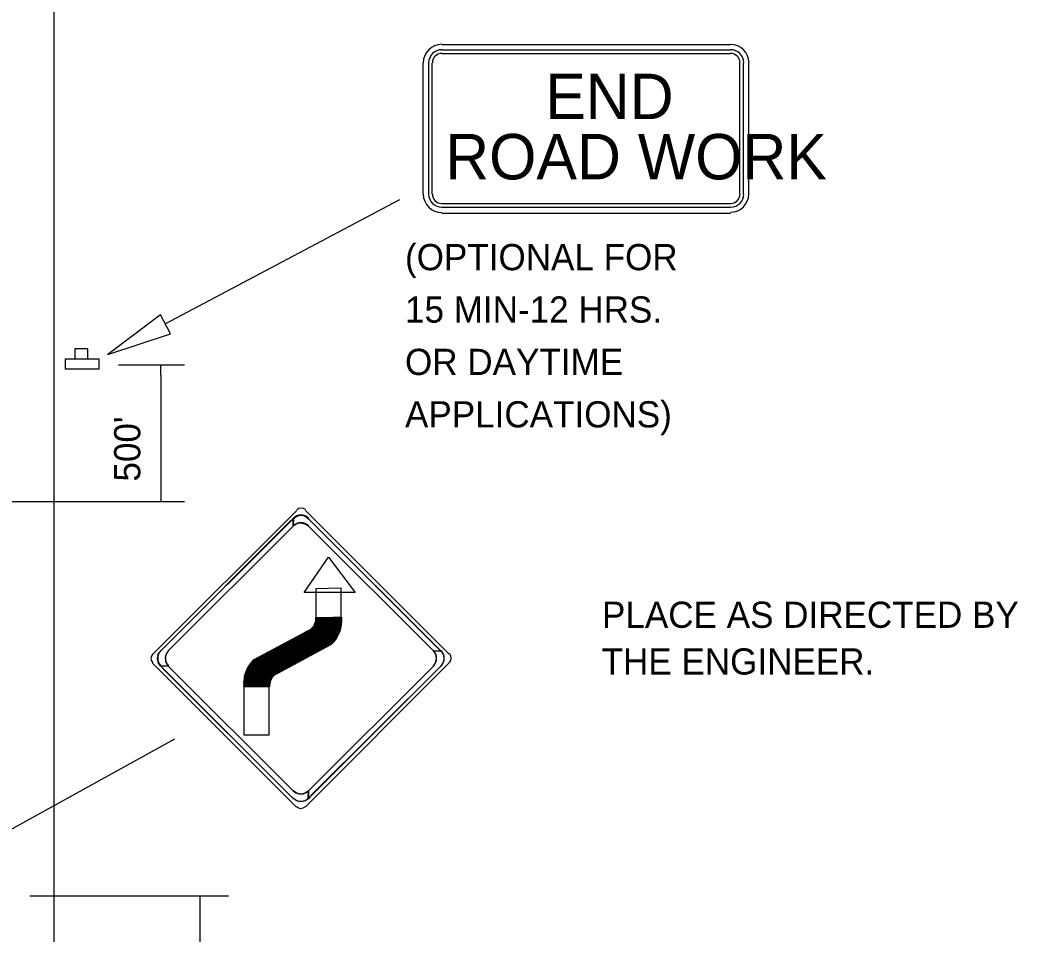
# Model space of a CAD drawing. Extents: x 15312.2 to 15319.5, y 15309 to 15319.2.
# Drawn here: x 15316.1 to 15318.384, y 15314.978 to 15317.071 of the extents above; entities that cross this region are included whole.
import ezdxf

# ---------------------------------------------------------------- set-up
doc = ezdxf.new("R2010")
doc.units = 0
for name, color, linetype in [('DETL-DIMS', 7, 'Continuous'), ('DETL-LINE', 7, 'Continuous'), ('DETL-NOTE', 7, 'Continuous'), ('USER-BORD', 7, 'Continuous')]:
    doc.layers.add(name, color=color, linetype=linetype)

# ---------------------------------------------------------------- blocks, each defined once
blk = doc.blocks.new('SIGN13')
at = {"layer": 'USER-BORD'}
for points in [[(-0.013, 0.018), (0.011, 0.019), (0.011, 0.037), (-0.013, 0.037)], [(-0.031, 0.018), (-0.031, 0), (0.032, 0), (0.032, 0.018)]]:
    blk.add_lwpolyline(points, close=True, dxfattribs=at)

msp = doc.modelspace()

# ---------------------------------------------------------------- linework, layer by layer
at = {"layer": 'DETL-DIMS'}
for p, q in [((15316.432, 15316.375), (15316.969, 15316.66)), ((15316.325, 15316.281), (15316.476, 15316.281)), ((15316.422, 15316.258), (15316.422, 15316.281)), ((15316.422, 15316.258), (15316.422, 15315.968)), ((15315.961, 15315.968), (15316.476, 15315.968)), ((15315.994, 15315.171), (15316.454, 15315.425)), ((15316.122, 15315.065), (15316.577, 15315.065)), ((15316.512, 15314.788), (15316.512, 15315.065))]:
    msp.add_line(p, q, dxfattribs=at)
msp.add_lwpolyline([(15316.444, 15316.352), (15316.421, 15316.396), (15316.301, 15316.305)], close=True, dxfattribs=at)
at = {"layer": 'DETL-LINE'}
for p, q in [((15316.177, 15318.785), (15316.177, 15310.694)), ((15317.726, 15317.014), (15317.065, 15317.014)), ((15317.726, 15317.002), (15317.065, 15317.002)), ((15317.065, 15316.994), (15317.726, 15316.994)), ((15317.726, 15317.002), (15317.726, 15317.002)), ((15317.022, 15316.972), (15317.022, 15316.672)), ((15317.035, 15316.972), (15317.035, 15316.672)), ((15317.043, 15316.672), (15317.043, 15316.972)), ((15317.747, 15316.972), (15317.747, 15316.672)), ((15317.756, 15316.672), (15317.756, 15316.972)), ((15317.768, 15316.672), (15317.768, 15316.972)), ((15317.726, 15316.65), (15317.065, 15316.65)), ((15317.065, 15316.642), (15317.726, 15316.642)), ((15317.065, 15316.629), (15317.726, 15316.629)), ((15316.733, 15315.948), (15316.403, 15315.618)), ((15317.082, 15315.619), (15316.753, 15315.948)), ((15316.422, 15315.626), (15316.725, 15315.929)), ((15316.725, 15315.912), (15316.439, 15315.626)), ((15316.76, 15315.929), (15317.063, 15315.626)), ((15317.046, 15315.626), (15316.76, 15315.912)), ((15316.813, 15315.641), (15316.771, 15315.683)), ((15316.814, 15315.642), (15316.772, 15315.684)), ((15316.816, 15315.645), (15316.773, 15315.688)), ((15316.815, 15315.644), (15316.773, 15315.686)), ((15316.814, 15315.642), (15316.773, 15315.685)), ((15316.815, 15315.643), (15316.773, 15315.685)), ((15316.817, 15315.646), (15316.774, 15315.689)), ((15316.818, 15315.647), (15316.774, 15315.689)), ((15316.82, 15315.649), (15316.775, 15315.693)), ((15316.819, 15315.648), (15316.775, 15315.692)), ((15316.819, 15315.647), (15316.775, 15315.69)), ((15316.823, 15315.653), (15316.776, 15315.699)), ((15316.822, 15315.652), (15316.776, 15315.698)), ((15316.821, 15315.652), (15316.776, 15315.697)), ((15316.821, 15315.651), (15316.776, 15315.695)), ((15316.82, 15315.65), (15316.776, 15315.694)), ((15316.824, 15315.655), (15316.777, 15315.703)), ((15316.835, 15315.703), (15316.777, 15315.702)), ((15316.824, 15315.654), (15316.777, 15315.701)), ((15316.825, 15315.656), (15316.778, 15315.703)), ((15316.825, 15315.656), (15316.779, 15315.703)), ((15316.825, 15315.657), (15316.781, 15315.703)), ((15316.826, 15315.658), (15316.782, 15315.703)), ((15316.827, 15315.659), (15316.783, 15315.703)), ((15316.827, 15315.661), (15316.785, 15315.703)), ((15316.828, 15315.661), (15316.787, 15315.703)), ((15316.828, 15315.662), (15316.788, 15315.703)), ((15316.829, 15315.663), (15316.789, 15315.703)), ((15316.829, 15315.664), (15316.791, 15315.703)), ((15316.829, 15315.666), (15316.792, 15315.703)), ((15316.83, 15315.666), (15316.794, 15315.703)), ((15316.83, 15315.667), (15316.795, 15315.703)), ((15316.831, 15315.668), (15316.797, 15315.703)), ((15316.831, 15315.67), (15316.798, 15315.703)), ((15316.831, 15315.671), (15316.8, 15315.703)), ((15316.832, 15315.671), (15316.801, 15315.703)), ((15316.832, 15315.673), (15316.802, 15315.703)), ((15316.833, 15315.674), (15316.804, 15315.703)), ((15316.833, 15315.675), (15316.806, 15315.703)), ((15316.834, 15315.676), (15316.806, 15315.703)), ((15316.834, 15315.677), (15316.808, 15315.703)), ((15316.834, 15315.679), (15316.81, 15315.703)), ((15316.834, 15315.68), (15316.811, 15315.703)), ((15316.834, 15315.68), (15316.812, 15315.703)), ((15316.834, 15315.682), (15316.814, 15315.703)), ((15316.834, 15315.683), (15316.815, 15315.703)), ((15316.835, 15315.685), (15316.817, 15315.703)), ((15316.835, 15315.686), (15316.818, 15315.703)), ((15316.835, 15315.687), (15316.82, 15315.703)), ((15316.835, 15315.689), (15316.821, 15315.703)), ((15316.835, 15315.689), (15316.823, 15315.703)), ((15316.835, 15315.691), (15316.824, 15315.703)), ((15316.836, 15315.693), (15316.825, 15315.703)), ((15316.836, 15315.694), (15316.827, 15315.703)), ((15316.836, 15315.695), (15316.829, 15315.703)), ((15316.836, 15315.697), (15316.829, 15315.703)), ((15316.835, 15315.699), (15316.831, 15315.703)), ((15316.835, 15315.7), (15316.833, 15315.703)), ((15316.835, 15315.702), (15316.834, 15315.703)), ((15316.768, 15315.677), (15316.635, 15315.606)), ((15316.776, 15315.621), (15316.736, 15315.661)), ((15316.777, 15315.622), (15316.737, 15315.661)), ((15316.778, 15315.622), (15316.739, 15315.661)), ((15316.778, 15315.623), (15316.74, 15315.662)), ((15316.78, 15315.624), (15316.74, 15315.662)), ((15316.781, 15315.624), (15316.741, 15315.663)), ((15316.782, 15315.624), (15316.742, 15315.664)), ((15316.782, 15315.624), (15316.743, 15315.664)), ((15316.783, 15315.625), (15316.744, 15315.665)), ((15316.784, 15315.626), (15316.745, 15315.665)), ((15316.786, 15315.626), (15316.746, 15315.666)), ((15316.787, 15315.627), (15316.747, 15315.666)), ((15316.787, 15315.627), (15316.748, 15315.666)), ((15316.788, 15315.628), (15316.749, 15315.667)), ((15316.789, 15315.628), (15316.75, 15315.667)), ((15316.79, 15315.628), (15316.751, 15315.668)), ((15316.791, 15315.629), (15316.752, 15315.669)), ((15316.792, 15315.63), (15316.753, 15315.669)), ((15316.794, 15315.631), (15316.754, 15315.671)), ((15316.793, 15315.63), (15316.754, 15315.67)), ((15316.795, 15315.631), (15316.755, 15315.671)), ((15316.796, 15315.632), (15316.756, 15315.671)), ((15316.797, 15315.633), (15316.758, 15315.671)), ((15316.799, 15315.633), (15316.759, 15315.673)), ((15316.797, 15315.633), (15316.759, 15315.672)), ((15316.8, 15315.634), (15316.76, 15315.673)), ((15316.801, 15315.634), (15316.761, 15315.674)), ((15316.801, 15315.635), (15316.762, 15315.674)), ((15316.802, 15315.635), (15316.764, 15315.675)), ((15316.803, 15315.636), (15316.764, 15315.675)), ((15316.805, 15315.637), (15316.765, 15315.675)), ((15316.806, 15315.637), (15316.766, 15315.676)), ((15316.806, 15315.638), (15316.767, 15315.677)), ((15316.808, 15315.638), (15316.768, 15315.678)), ((15316.807, 15315.638), (15316.768, 15315.677)), ((15316.81, 15315.639), (15316.769, 15315.68)), ((15316.809, 15315.639), (15316.769, 15315.679)), ((15316.811, 15315.64), (15316.77, 15315.68)), ((15316.812, 15315.641), (15316.771, 15315.681)), ((15316.812, 15315.641), (15316.679, 15315.569)), ((15316.733, 15315.598), (15316.693, 15315.638)), ((15316.732, 15315.598), (15316.693, 15315.638)), ((15316.734, 15315.599), (15316.695, 15315.638)), ((15316.735, 15315.599), (15316.696, 15315.638)), ((15316.736, 15315.6), (15316.697, 15315.639)), ((15316.738, 15315.6), (15316.698, 15315.64)), ((15316.737, 15315.6), (15316.698, 15315.64)), ((15316.739, 15315.601), (15316.699, 15315.641)), ((15316.74, 15315.602), (15316.7, 15315.641)), ((15316.741, 15315.602), (15316.702, 15315.642)), ((15316.743, 15315.603), (15316.703, 15315.642)), ((15316.742, 15315.603), (15316.703, 15315.642)), ((15316.744, 15315.604), (15316.704, 15315.643)), ((15316.745, 15315.605), (15316.705, 15315.644)), ((15316.745, 15315.605), (15316.706, 15315.644)), ((15316.746, 15315.605), (15316.707, 15315.645)), ((15316.748, 15315.606), (15316.708, 15315.645)), ((15316.749, 15315.606), (15316.709, 15315.646)), ((15316.75, 15315.607), (15316.71, 15315.647)), ((15316.75, 15315.607), (15316.711, 15315.647)), ((15316.751, 15315.608), (15316.712, 15315.647)), ((15316.752, 15315.609), (15316.712, 15315.647)), ((15316.753, 15315.609), (15316.714, 15315.648)), ((15316.754, 15315.61), (15316.715, 15315.649)), ((15316.755, 15315.61), (15316.716, 15315.649)), ((15316.757, 15315.611), (15316.717, 15315.651)), ((15316.756, 15315.61), (15316.717, 15315.65)), ((15316.758, 15315.611), (15316.718, 15315.651)), ((15316.759, 15315.612), (15316.72, 15315.652)), ((15316.76, 15315.613), (15316.721, 15315.652)), ((15316.761, 15315.613), (15316.721, 15315.652)), ((15316.762, 15315.614), (15316.722, 15315.653)), ((15316.763, 15315.614), (15316.723, 15315.653)), ((15316.764, 15315.614), (15316.724, 15315.654)), ((15316.764, 15315.615), (15316.725, 15315.654)), ((15316.765, 15315.615), (15316.726, 15315.655)), ((15316.767, 15315.616), (15316.727, 15315.656)), ((15316.768, 15315.617), (15316.728, 15315.656)), ((15316.768, 15315.617), (15316.729, 15315.656)), ((15316.769, 15315.618), (15316.73, 15315.657)), ((15316.771, 15315.619), (15316.731, 15315.658)), ((15316.77, 15315.618), (15316.731, 15315.657)), ((15316.772, 15315.619), (15316.733, 15315.658)), ((15316.773, 15315.619), (15316.734, 15315.659)), ((15316.774, 15315.62), (15316.735, 15315.66)), ((15316.775, 15315.62), (15316.735, 15315.66)), ((15316.691, 15315.575), (15316.651, 15315.615)), ((15316.692, 15315.576), (15316.652, 15315.615)), ((15316.693, 15315.577), (15316.653, 15315.616)), ((15316.693, 15315.577), (15316.654, 15315.616)), ((15316.694, 15315.577), (15316.655, 15315.617)), ((15316.697, 15315.578), (15316.656, 15315.618)), ((15316.695, 15315.577), (15316.656, 15315.618)), ((15316.698, 15315.579), (15316.658, 15315.619)), ((15316.698, 15315.579), (15316.659, 15315.619)), ((15316.7, 15315.581), (15316.66, 15315.62)), ((15316.699, 15315.58), (15316.66, 15315.619)), ((15316.701, 15315.581), (15316.661, 15315.62)), ((15316.702, 15315.581), (15316.662, 15315.621)), ((15316.703, 15315.581), (15316.663, 15315.621)), ((15316.705, 15315.583), (15316.665, 15315.623)), ((15316.704, 15315.582), (15316.665, 15315.622)), ((15316.706, 15315.583), (15316.666, 15315.623)), ((15316.707, 15315.584), (15316.667, 15315.624)), ((15316.707, 15315.585), (15316.668, 15315.624)), ((15316.708, 15315.585), (15316.669, 15315.624)), ((15316.71, 15315.586), (15316.67, 15315.625)), ((15316.711, 15315.586), (15316.671, 15315.625)), ((15316.712, 15315.586), (15316.672, 15315.626)), ((15316.712, 15315.587), (15316.673, 15315.627)), ((15316.714, 15315.588), (15316.674, 15315.628)), ((15316.713, 15315.587), (15316.674, 15315.627)), ((15316.715, 15315.588), (15316.675, 15315.628)), ((15316.717, 15315.589), (15316.677, 15315.628)), ((15316.717, 15315.59), (15316.678, 15315.629)), ((15316.719, 15315.591), (15316.679, 15315.63)), ((15316.718, 15315.59), (15316.679, 15315.629)), ((15316.72, 15315.591), (15316.68, 15315.631)), ((15316.721, 15315.591), (15316.681, 15315.631)), ((15316.722, 15315.592), (15316.683, 15315.632)), ((15316.724, 15315.593), (15316.684, 15315.633)), ((15316.723, 15315.592), (15316.684, 15315.632)), ((15316.725, 15315.594), (15316.685, 15315.633)), ((15316.726, 15315.594), (15316.686, 15315.633)), ((15316.726, 15315.595), (15316.687, 15315.634)), ((15316.727, 15315.595), (15316.688, 15315.634)), ((15316.729, 15315.595), (15316.689, 15315.635)), ((15316.73, 15315.596), (15316.69, 15315.636)), ((15316.731, 15315.596), (15316.691, 15315.636)), ((15316.731, 15315.597), (15316.692, 15315.637)), ((15316.403, 15315.598), (15316.732, 15315.269)), ((15316.67, 15315.546), (15316.623, 15315.593)), ((15316.67, 15315.544), (15316.623, 15315.592)), ((15316.67, 15315.548), (15316.624, 15315.594)), ((15316.67, 15315.55), (15316.625, 15315.595)), ((15316.67, 15315.548), (15316.625, 15315.595)), ((15316.67, 15315.552), (15316.626, 15315.596)), ((15316.671, 15315.555), (15316.627, 15315.599)), ((15316.671, 15315.553), (15316.627, 15315.598)), ((15316.671, 15315.553), (15316.627, 15315.597)), ((15316.672, 15315.556), (15316.628, 15315.6)), ((15316.672, 15315.558), (15316.629, 15315.6)), ((15316.673, 15315.558), (15316.63, 15315.601)), ((15316.674, 15315.56), (15316.631, 15315.603)), ((15316.673, 15315.559), (15316.631, 15315.602)), ((15316.674, 15315.563), (15316.632, 15315.605)), ((15316.674, 15315.562), (15316.632, 15315.604)), ((15316.675, 15315.563), (15316.633, 15315.605)), ((15316.675, 15315.564), (15316.634, 15315.605)), ((15316.676, 15315.565), (15316.635, 15315.606)), ((15316.677, 15315.566), (15316.636, 15315.607)), ((15316.678, 15315.567), (15316.637, 15315.608)), ((15316.677, 15315.567), (15316.637, 15315.607)), ((15316.679, 15315.568), (15316.639, 15315.609)), ((15316.679, 15315.569), (15316.64, 15315.609)), ((15316.68, 15315.57), (15316.641, 15315.61)), ((15316.682, 15315.571), (15316.642, 15315.61)), ((15316.681, 15315.57), (15316.642, 15315.61)), ((15316.683, 15315.571), (15316.643, 15315.611)), ((15316.684, 15315.572), (15316.644, 15315.611)), ((15316.686, 15315.572), (15316.646, 15315.612)), ((15316.685, 15315.572), (15316.646, 15315.612)), ((15316.687, 15315.573), (15316.647, 15315.613)), ((15316.688, 15315.574), (15316.648, 15315.614)), ((15316.688, 15315.574), (15316.649, 15315.614)), ((15316.689, 15315.575), (15316.65, 15315.614)), ((15316.753, 15315.269), (15317.082, 15315.599)), ((15316.725, 15315.288), (15316.422, 15315.591)), ((15316.439, 15315.591), (15316.725, 15315.306)), ((15316.642, 15315.544), (15316.613, 15315.572)), ((15316.641, 15315.544), (15316.613, 15315.571)), ((15316.639, 15315.544), (15316.613, 15315.569)), ((15316.645, 15315.544), (15316.614, 15315.574)), ((15316.643, 15315.544), (15316.614, 15315.573)), ((15316.648, 15315.544), (15316.615, 15315.577)), ((15316.646, 15315.544), (15316.615, 15315.575)), ((15316.651, 15315.544), (15316.616, 15315.578)), ((15316.649, 15315.544), (15316.616, 15315.577)), ((15316.654, 15315.544), (15316.617, 15315.581)), ((15316.652, 15315.544), (15316.617, 15315.58)), ((15316.66, 15315.544), (15316.618, 15315.585)), ((15316.658, 15315.544), (15316.618, 15315.583)), ((15316.656, 15315.544), (15316.618, 15315.582)), ((15316.656, 15315.544), (15316.618, 15315.581)), ((15316.661, 15315.544), (15316.619, 15315.586)), ((15316.664, 15315.544), (15316.62, 15315.587)), ((15316.662, 15315.544), (15316.62, 15315.586)), ((15316.667, 15315.544), (15316.621, 15315.589)), ((15316.665, 15315.544), (15316.621, 15315.588)), ((15316.668, 15315.544), (15316.622, 15315.591)), ((15316.67, 15315.544), (15316.623, 15315.591)), ((15317.063, 15315.591), (15316.76, 15315.288)), ((15316.76, 15315.306), (15317.046, 15315.591)), ((15316.626, 15315.544), (15316.611, 15315.558)), ((15316.624, 15315.544), (15316.611, 15315.557)), ((15316.623, 15315.544), (15316.611, 15315.556)), ((15316.622, 15315.544), (15316.611, 15315.554)), ((15316.62, 15315.544), (15316.611, 15315.553)), ((15316.618, 15315.544), (15316.611, 15315.551)), ((15316.617, 15315.544), (15316.611, 15315.55)), ((15316.616, 15315.544), (15316.611, 15315.548)), ((15316.614, 15315.544), (15316.611, 15315.547)), ((15316.632, 15315.544), (15316.612, 15315.563)), ((15316.63, 15315.544), (15316.612, 15315.563)), ((15316.629, 15315.544), (15316.612, 15315.561)), ((15316.627, 15315.544), (15316.612, 15315.559)), ((15316.637, 15315.544), (15316.613, 15315.568)), ((15316.636, 15315.544), (15316.613, 15315.567)), ((15316.635, 15315.544), (15316.613, 15315.566)), ((15316.633, 15315.544), (15316.613, 15315.565)), ((15316.613, 15315.544), (15316.611, 15315.545)), ((15316.67, 15315.544), (15316.612, 15315.544))]:
    msp.add_line(p, q, dxfattribs=at)
for points in [[(15316.76, 15315.929), (15317.054, 15315.635), (15317.064, 15315.625), (15317.046, 15315.626), (15316.76, 15315.912), (15316.754, 15315.916), (15316.744, 15315.919), (15316.736, 15315.918), (15316.73, 15315.916), (15316.725, 15315.912), (15316.725, 15315.929), (15316.732, 15315.934), (15316.741, 15315.937), (15316.748, 15315.936), (15316.754, 15315.934)], [(15316.422, 15315.626), (15316.716, 15315.921), (15316.726, 15315.93), (15316.725, 15315.912), (15316.439, 15315.626), (15316.435, 15315.62), (15316.432, 15315.611), (15316.433, 15315.603), (15316.435, 15315.597), (15316.439, 15315.591), (15316.422, 15315.591), (15316.417, 15315.598), (15316.414, 15315.608), (15316.415, 15315.615), (15316.417, 15315.621)], [(15316.806, 15315.841), (15316.867, 15315.76), (15316.75, 15315.76)], [(15316.835, 15315.77), (15316.777, 15315.768), (15316.777, 15315.702), (15316.835, 15315.704)], [(15317.063, 15315.591), (15316.768, 15315.297), (15316.759, 15315.287), (15316.76, 15315.306), (15317.046, 15315.591), (15317.05, 15315.597), (15317.053, 15315.607), (15317.052, 15315.615), (15317.05, 15315.621), (15317.046, 15315.626), (15317.063, 15315.626), (15317.068, 15315.619), (15317.07, 15315.61), (15317.069, 15315.603), (15317.067, 15315.597)], [(15316.725, 15315.288), (15316.43, 15315.583), (15316.421, 15315.592), (15316.439, 15315.591), (15316.725, 15315.306), (15316.731, 15315.301), (15316.74, 15315.298), (15316.748, 15315.299), (15316.754, 15315.301), (15316.76, 15315.306), (15316.76, 15315.288), (15316.753, 15315.283), (15316.743, 15315.281), (15316.736, 15315.282), (15316.731, 15315.284)], [(15316.67, 15315.434), (15316.67, 15315.548), (15316.612, 15315.548), (15316.612, 15315.434)]]:
    msp.add_lwpolyline(points, close=True, dxfattribs=at)
for centre, radius, start, end in [((15317.0652, 15316.9729), 0.0424, 90, 180), ((15317.7264, 15316.9729), 0.0421, 0, 90), ((15317.0652, 15316.9729), 0.0301, 90, 180), ((15317.0652, 15316.9729), 0.0216, 90, 180), ((15317.7264, 15316.9729), 0.0301, 0, 90), ((15317.7264, 15316.9729), 0.0216, 0, 90), ((15317.0652, 15316.6724), 0.0424, 180, 270), ((15317.0652, 15316.6724), 0.0301, 180, 270), ((15317.0652, 15316.6724), 0.0216, 180, 270), ((15317.7264, 15316.6724), 0.0415, 270, 0), ((15317.7264, 15316.6724), 0.0216, 270, 0), ((15317.7264, 15316.6724), 0.0301, 270, 0), ((15316.7428, 15315.9126), 0.0247, 45, 135), ((15316.7435, 15315.9387), 0.0144, 45, 135), ((15316.7427, 15315.8951), 0.0247, 45, 135), ((15316.7412, 15315.7013), 0.0357, 318.0904, 2.5865), ((15316.7613, 15315.6957), 0.0751, 313.5014, 5.8992), ((15316.4138, 15315.609), 0.0144, 135, 225), ((15316.4396, 15315.6094), 0.0247, 135, 225), ((15316.457, 15315.6094), 0.0247, 135, 225), ((15317.0285, 15315.6094), 0.0247, 315, 45), ((15317.046, 15315.6094), 0.0247, 315, 45), ((15317.0725, 15315.6097), 0.0144, 315, 45), ((15316.6869, 15315.5522), 0.0751, 133.5014, 185.8992), ((15316.7066, 15315.5458), 0.0357, 138.0904, 182.5865), ((15316.7428, 15315.3237), 0.0247, 225, 315), ((15316.7428, 15315.3062), 0.0247, 225, 315), ((15316.7428, 15315.28), 0.0144, 225, 315)]:
    msp.add_arc(centre, radius, start, end, dxfattribs=at)

# ---------------------------------------------------------------- block references
at = {"layer": 'DETL-LINE', "xscale": 1.236689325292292, "yscale": 1.236689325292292}
msp.add_blockref('SIGN13', (15316.241, 15316.272), dxfattribs=at)

# ---------------------------------------------------------------- texts
at = {"layer": 'DETL-LINE'}
for s, p in [('END', (15317.302, 15316.844)), ('ROAD WORK', (15317.073, 15316.706))]:
    msp.add_text(s, height=0.1041, rotation=360, dxfattribs=at).set_placement(p)
at = {"layer": 'DETL-NOTE'}
for s, p in [('(OPTIONAL FOR', (15316.981, 15316.498)), ('15 MIN-12 HRS. ', (15316.981, 15316.378)), ('OR DAYTIME', (15316.981, 15316.258)), ('APPLICATIONS)', (15316.981, 15316.138)), ('PLACE AS DIRECTED BY', (15317.432, 15315.679)), ('THE ENGINEER.', (15317.431, 15315.572))]:
    msp.add_text(s, height=0.06, dxfattribs=at).set_placement(p)
msp.add_text("500'", height=0.06, rotation=90, dxfattribs=at).set_placement((15316.375, 15316.014))

doc.saveas('drawing.dxf')
